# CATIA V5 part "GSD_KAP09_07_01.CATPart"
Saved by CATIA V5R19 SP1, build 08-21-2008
Part number: GSD_REPETITION_06
Description: Beispielmodell: Duplizieren eines geometrischen Sets  Maik Hertha IT Consultants
Bounding box of the stored display mesh (mm): x -29.841 to 75.347, y -10 to 40, z 36.232 to 56.986
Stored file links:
  C:\Users\Maik\CAD Daten\modelle\gsd_buch_uebung\GSD_KAP09_07_01.CATPart
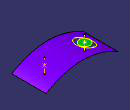
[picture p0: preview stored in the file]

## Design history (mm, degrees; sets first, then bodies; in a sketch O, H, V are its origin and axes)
AxisSystem1 "Absolute Axis System": origin (0, 0, 0), X (1, 0, 0), Y (0, 1, 0), Z (0, 0, 1)
Set1 "Work"
  Plane1: type Equation, A 0, B 1, C 0, Length -10
  Point1: type OnPlane, Support Plane1, Direction (-1, 0, 0), H -16.666, V 8.006
  Sketch1 on Plane1, origin (16.666, -10, 8.006), H (-1, 0, 0), V (0, 0, 1)
    spline S1 through (-58.6807, 28.2259) (-5.4892, 43.7462) (46.5071, 28.2259)
    curve C1
  Extrude1: Lim1 50, Lim2 0, Element1 Sketch1.C1, Direction Plane1
  Set2 "Basis"
    Point2 "Referenzpunkt.1": stored without definition
    Line1 "Ausrichtung.1": type PtDir, Direction (0, 0, 1), Start -10, End 10, RefPoint Point2
    Plane2: type Normal, Curve Line1, RefPoint Point2
    Set3 "Quelle"
      Sketch2 on Plane2, origin (-6.428, 14.4636, 46.9865), H (0, -1, 0), V (1, 0, 0)
        circle A1 centre (0, 0) radius 7.5
        radius A1 = 7.5
      Split1: ToCut Plane2, Intersections {intersect ToIntersect1 Plane2, ToIntersect2 Sketch2}, Cutting Sketch2
      Extrude2: Lim1 13, Lim2 13, Element1 Sketch2, Direction Plane2
      Offset1: Length 5, Offset Extrude2
  Split2: ToCut Extrude1, Intersections {intersect ToIntersect1 Extrude1, ToIntersect2 Offset1}, Cutting Offset1
  Set4 "Ziel"
    Point3 "Referenzpunkt.2": stored without definition
    Line2 "Ausrichtung.2": type PtDir, Direction (0, 0, 1), Start -10, End 10, RefPoint Point3
    Plane3: type Normal, Curve Line2, RefPoint Point3
Body1 (main body)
